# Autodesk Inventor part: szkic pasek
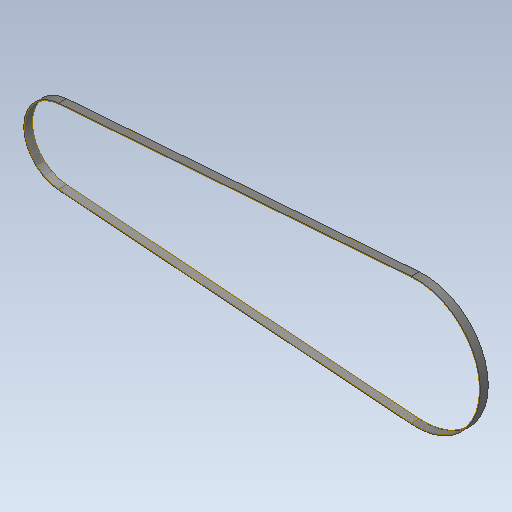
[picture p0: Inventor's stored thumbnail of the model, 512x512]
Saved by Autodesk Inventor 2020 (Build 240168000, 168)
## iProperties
Created: 2015-11
Part Number: szkic pasek
Material: solidworks materials|Guma|79
Document SubType Name: Modeling
Designer: Tomasz
Density: 1 g/cm^3
Appearance: 76,76,76
Sending System: SolidWorks 2017
Last Author: Tomasz
Last Saved: 2017-11-19
Author: Tomasz
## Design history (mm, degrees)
feature "Imported1"
feature "Surface-Imported1"
node "Bryła1"
body "Srf1"
